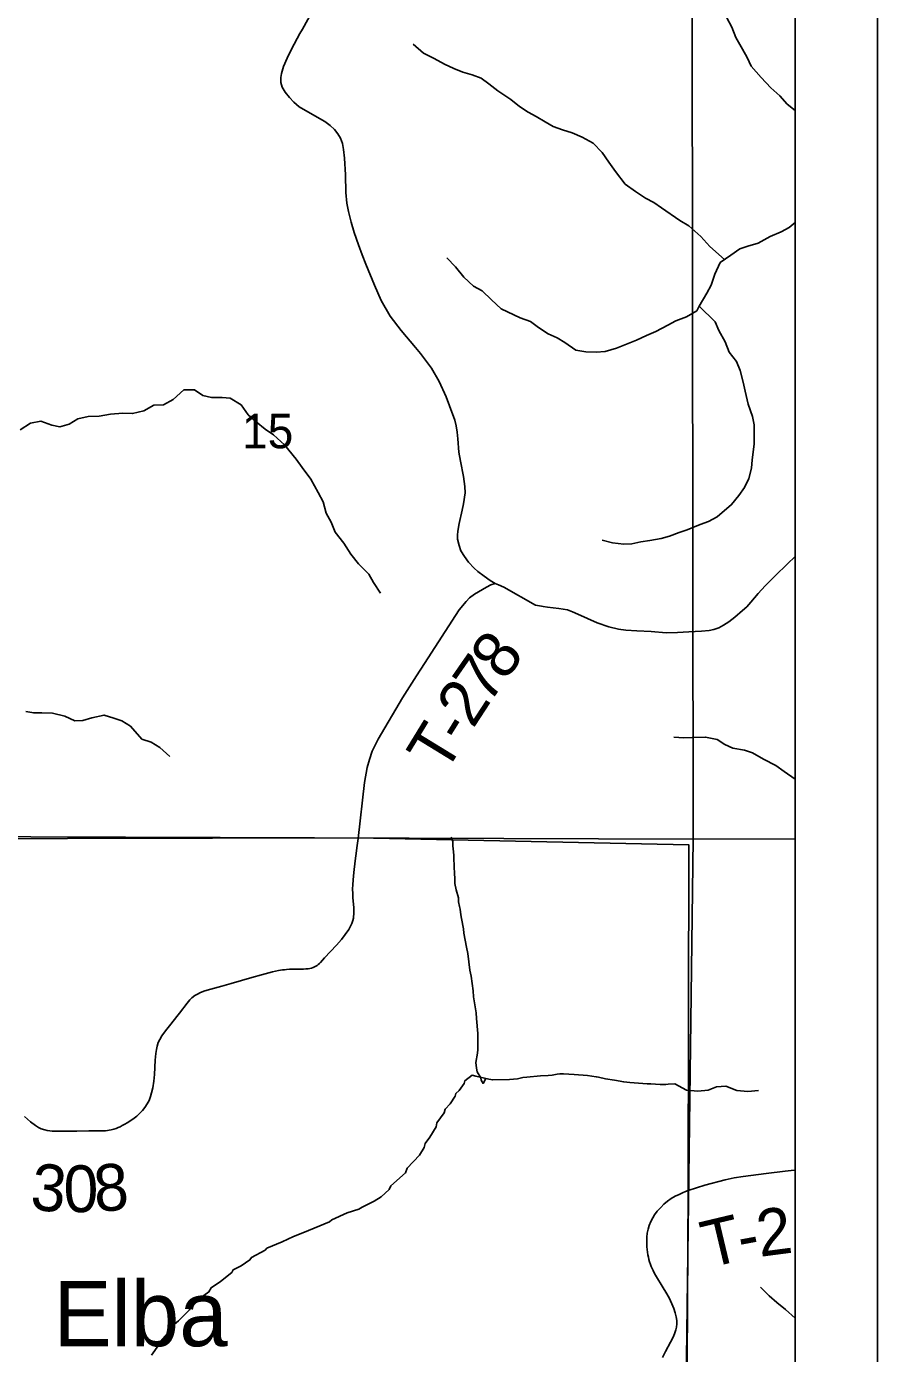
# Model space of a CAD drawing. Extents: x 0 to 34, y 0 to 22.
# Drawn here: x 7.967 to 9, y 14.985 to 16.596 of the extents above; entities that cross this region are included whole.
import ezdxf

# ---------------------------------------------------------------- set-up
doc = ezdxf.new("R2010")
doc.units = 0
for name, color, linetype in [('Default', 7, 'Continuous'), ('GM_X_Minor_River', 7, 'Continuous'), ('GM_X_Rail_Line', 7, 'Continuous'), ('GM_X_Section', 7, 'Continuous'), ('GM_X_Section_Text', 7, 'Continuous'), ('GM_X_Township_Road', 7, 'Continuous'), ('GM_X_Township_Road_Text', 7, 'Continuous'), ('GM_X_Unincorporated_Text', 7, 'Continuous'), ('SH_Cut_Line', 7, 'Continuous'), ('SH_Data', 7, 'Continuous')]:
    doc.layers.add(name, color=color, linetype=linetype)

msp = doc.modelspace()

# ---------------------------------------------------------------- linework, layer by layer
at = {"layer": 'Default'}
for points in [[(8.9, 15.6097), (8.9, 16.6172), (8.7751, 16.6184), (8.7763, 15.6092)], [(8.9, 14.6299), (8.9, 15.6097), (8.7763, 15.6092), (8.7636, 14.6322)]]:
    msp.add_lwpolyline(points, close=True, dxfattribs=at)
at = {"layer": 'GM_X_Minor_River'}
for points in [[(8.9, 16.4939), (8.9, 16.4939), (8.8904, 16.5018), (8.8813, 16.512), (8.8706, 16.5214), (8.8587, 16.5342), (8.8465, 16.5478), (8.8418, 16.5584), (8.8361, 16.5686), (8.828, 16.5826), (8.823, 16.5954), (8.8169, 16.6064)], [(8.8142, 16.313), (8.7963, 16.329), (8.7856, 16.3411), (8.7711, 16.3539), (8.76, 16.3606), (8.7379, 16.3757), (8.7283, 16.3824), (8.7184, 16.3877), (8.7062, 16.3956), (8.6936, 16.4046), (8.6818, 16.42), (8.6737, 16.4314), (8.6657, 16.4431), (8.6546, 16.4544), (8.6412, 16.4615), (8.6294, 16.4671), (8.6176, 16.4705), (8.6062, 16.4745), (8.5963, 16.4802), (8.5856, 16.4869), (8.5757, 16.4922), (8.5651, 16.4989), (8.5548, 16.5072), (8.5391, 16.5177), (8.528, 16.5264), (8.5185, 16.5331), (8.5079, 16.5372), (8.4964, 16.5406), (8.4854, 16.5451), (8.474, 16.5503), (8.4618, 16.557), (8.4488, 16.5638), (8.4362, 16.5747)], [(8.7835, 16.2563), (8.7929, 16.2721), (8.7981, 16.282), (8.8026, 16.2953), (8.8089, 16.3094), (8.8218, 16.3182), (8.8327, 16.3262), (8.8426, 16.3293), (8.8551, 16.3328), (8.8695, 16.3409), (8.8831, 16.3466), (8.8929, 16.352), (8.9, 16.358)], [(8.5431, 16.2534), (8.5313, 16.2643), (8.5198, 16.2749), (8.5092, 16.2809), (8.4977, 16.2918), (8.4874, 16.3042), (8.477, 16.3152)], [(8.7835, 16.2563), (8.7805, 16.2509), (8.768, 16.2437), (8.7551, 16.2386), (8.7453, 16.2332), (8.731, 16.2258), (8.7193, 16.2208), (8.7072, 16.215), (8.6831, 16.2056), (8.6691, 16.2016), (8.6585, 16.2008), (8.646, 16.201), (8.6335, 16.2032), (8.6205, 16.2125), (8.6109, 16.2181), (8.6002, 16.2229), (8.5884, 16.2307), (8.5785, 16.2378), (8.5659, 16.2422), (8.5431, 16.2534)], [(8.7835, 16.2563), (8.8029, 16.2376), (8.8072, 16.2271), (8.8149, 16.2131), (8.82, 16.2006), (8.8288, 16.1894), (8.8331, 16.1784), (8.8367, 16.164), (8.8395, 16.1531), (8.8431, 16.1375), (8.8482, 16.1224), (8.8502, 16.1122), (8.8503, 16.1027), (8.8501, 16.0894), (8.849, 16.0792), (8.848, 16.0697), (8.847, 16.0598), (8.8437, 16.0473), (8.8385, 16.0362), (8.8318, 16.0266), (8.8229, 16.0155), (8.8052, 16.0006), (8.7947, 15.9951), (8.7845, 15.9912), (8.769, 15.985), (8.7592, 15.9818), (8.7475, 15.9772), (8.7373, 15.9744), (8.7237, 15.972), (8.7127, 15.9703), (8.7017, 15.9679), (8.6919, 15.9675), (8.6782, 15.9692), (8.6656, 15.9725)], [(7.959, 16.1063), (7.9714, 16.1144), (7.9839, 16.1168), (7.9972, 16.112), (8.0071, 16.1098), (8.0185, 16.113), (8.029, 16.1195), (8.0415, 16.1227), (8.0547, 16.1229), (8.0684, 16.1253), (8.0835, 16.1266), (8.0953, 16.126), (8.1089, 16.1295), (8.1213, 16.1361), (8.1327, 16.1366), (8.1447, 16.1432), (8.1575, 16.1547), (8.1704, 16.1549), (8.1807, 16.1478), (8.191, 16.1456), (8.2042, 16.1454), (8.2137, 16.1447), (8.2271, 16.1365), (8.2359, 16.1245), (8.2455, 16.1162), (8.2562, 16.1072), (8.2665, 16.1001), (8.2799, 16.0881), (8.2942, 16.0705), (8.3015, 16.0607), (8.3119, 16.0464), (8.3208, 16.0302), (8.327, 16.0189), (8.3305, 16.0052), (8.3367, 15.9943), (8.3414, 15.9822), (8.3518, 15.9687), (8.3603, 15.9555), (8.3699, 15.9438), (8.3822, 15.9311), (8.388, 15.9209), (8.3965, 15.9081)], [(7.9656, 15.7645), (7.9754, 15.7627), (7.9853, 15.7629), (7.9982, 15.7622), (8.013, 15.7586), (8.0252, 15.753), (8.0351, 15.7535), (8.046, 15.7567), (8.0608, 15.7599), (8.0726, 15.7562), (8.0824, 15.7529), (8.0928, 15.7466), (8.1066, 15.7308), (8.118, 15.7271), (8.1283, 15.7208), (8.1406, 15.7095)], [(8.9, 15.6822), (8.8868, 15.6915), (8.8765, 15.6986), (8.8616, 15.7064), (8.8483, 15.7142), (8.8384, 15.7175), (8.8243, 15.72), (8.8148, 15.7241), (8.8053, 15.7305), (8.7912, 15.7333), (8.7749, 15.7328), (8.765, 15.7323), (8.7525, 15.7333)], [(8.5245, 15.3189), (8.5211, 15.3127), (8.5187, 15.3168), (8.5183, 15.3195), (8.514, 15.327), (8.5132, 15.3312), (8.5123, 15.338), (8.5144, 15.3494), (8.5147, 15.354), (8.5148, 15.3673), (8.5147, 15.3734), (8.5129, 15.3916), (8.5128, 15.3984), (8.5094, 15.4177), (8.5089, 15.4253), (8.5067, 15.4431), (8.505, 15.4503), (8.5024, 15.4704), (8.5008, 15.478), (8.4978, 15.4951), (8.4973, 15.5004), (8.4948, 15.5129), (8.494, 15.5174), (8.4931, 15.5242), (8.4923, 15.5276), (8.4911, 15.5333), (8.491, 15.5379), (8.4882, 15.5477), (8.4869, 15.5557), (8.4868, 15.5591), (8.4863, 15.5701), (8.4858, 15.5735), (8.4855, 15.5895), (8.4851, 15.594), (8.4842, 15.6012), (8.4841, 15.6065), (8.4821, 15.6118)], [(8.1183, 14.9827), (8.1272, 14.9953), (8.1294, 14.9995), (8.1406, 15.0123), (8.142, 15.0168), (8.151, 15.0246), (8.1645, 15.0377), (8.1666, 15.0438), (8.188, 15.0597), (8.1906, 15.0647), (8.2022, 15.0721), (8.2157, 15.083), (8.2175, 15.0864), (8.2273, 15.0911), (8.2378, 15.0985), (8.2396, 15.1016), (8.2562, 15.1102), (8.2584, 15.1129), (8.2769, 15.1204), (8.2908, 15.1271), (8.3021, 15.1314), (8.3157, 15.137), (8.3346, 15.1449), (8.3372, 15.1472), (8.356, 15.1558), (8.37, 15.1599), (8.3741, 15.1626), (8.3888, 15.1697), (8.3971, 15.1751), (8.4071, 15.184), (8.409, 15.1886), (8.4269, 15.2041), (8.4287, 15.2098), (8.444, 15.2256), (8.4495, 15.2348), (8.4506, 15.2398), (8.4565, 15.2475), (8.4639, 15.2601), (8.465, 15.2651), (8.4739, 15.277), (8.4749, 15.2816), (8.4809, 15.2881), (8.4872, 15.2973), (8.4879, 15.3004), (8.492, 15.3043), (8.4979, 15.3127), (8.499, 15.3161), (8.5076, 15.3227), (8.5122, 15.3217), (8.5282, 15.3181), (8.5328, 15.3171), (8.5533, 15.3174), (8.5627, 15.3183), (8.5692, 15.3199), (8.5741, 15.3204), (8.5908, 15.3218), (8.5999, 15.3223), (8.6048, 15.3227), (8.6112, 15.324), (8.6143, 15.3244), (8.6188, 15.3245), (8.6317, 15.3235), (8.6477, 15.3223), (8.6584, 15.3209), (8.6614, 15.3202), (8.6698, 15.3185), (8.6808, 15.3167), (8.6919, 15.3146), (8.6991, 15.314), (8.7097, 15.313), (8.7204, 15.3124), (8.7249, 15.3121), (8.736, 15.3115), (8.7428, 15.3116), (8.7458, 15.3117), (8.7538, 15.3122), (8.7679, 15.3044)], [(8.7679, 15.3044), (8.7817, 15.3034), (8.7945, 15.3047), (8.8044, 15.3086), (8.8157, 15.3095), (8.8294, 15.3043), (8.8427, 15.303), (8.8556, 15.3042)], [(8.9, 15.0278), (8.8882, 15.0383), (8.8778, 15.0469), (8.8683, 15.0548), (8.8579, 15.0653)]]:
    msp.add_lwpolyline(points, dxfattribs=at)
at = {"layer": 'GM_X_Rail_Line'}
for points in [[(5.9824, 16.6436), (7.149, 16.6283), (7.6814, 16.6224), (7.7376, 16.622), (7.7377, 16.1663), (7.7446, 16.1373), (7.7538, 15.9954), (7.756, 15.9342), (7.7526, 15.9181), (7.7434, 15.892), (7.7355, 15.6105), (7.8392, 15.6096), (8.369, 15.6108), (8.7708, 15.6025), (8.77, 15.1835), (8.767, 14.6265), (8.9, 14.624), (8.9, 20.9)], [(4.5781, 14.1), (8.76, 14.1), (8.766, 14.6043), (8.767, 14.6265), (8.77, 15.1835), (8.7708, 15.6025), (8.369, 15.6108), (7.8392, 15.6096), (7.7355, 15.6105), (7.7434, 15.892), (7.7526, 15.9181), (7.756, 15.9342), (7.7538, 15.9954), (7.7446, 16.1373), (7.7377, 16.1663), (7.7376, 16.622), (7.6814, 16.6224), (7.149, 16.6283), (5.9824, 16.6436)]]:
    msp.add_lwpolyline(points, dxfattribs=at)
at = {"layer": 'GM_X_Section'}
msp.add_lwpolyline([(7.7506, 16.628), (8.7751, 16.6184), (8.7763, 15.6092), (7.7414, 15.613)], close=True, dxfattribs=at)
at = {"layer": 'GM_X_Township_Road'}
for points in [[(8.3172, 16.6207), (8.3016, 16.5926), (8.2986, 16.5876), (8.2884, 16.5683), (8.2831, 16.5574), (8.2788, 16.5476), (8.2761, 16.5389), (8.2754, 16.534), (8.2755, 16.5282), (8.2771, 16.5224), (8.2805, 16.5163), (8.2859, 16.51), (8.291, 16.5043), (8.2978, 16.4985), (8.3054, 16.4939), (8.3289, 16.4806), (8.3355, 16.4757), (8.3407, 16.4708), (8.3448, 16.4656), (8.3478, 16.4605), (8.3503, 16.454), (8.3517, 16.4468), (8.3527, 16.4361), (8.3538, 16.4161), (8.3542, 16.3945), (8.3556, 16.3815), (8.3574, 16.3714), (8.3609, 16.3585), (8.3646, 16.3458), (8.3699, 16.3311), (8.3742, 16.3189), (8.3787, 16.3074), (8.3891, 16.2818), (8.3971, 16.2632), (8.408, 16.2444), (8.4215, 16.2269), (8.439, 16.2064), (8.4452, 16.1991), (8.4583, 16.1813), (8.4676, 16.165), (8.476, 16.1462), (8.4801, 16.1355), (8.4866, 16.1182), (8.4885, 16.1112), (8.4897, 16.1033), (8.4902, 16.0952), (8.4917, 16.0792), (8.4934, 16.0682), (8.4971, 16.0495), (8.4989, 16.0375), (8.4993, 16.0299), (8.4973, 16.0164), (8.4956, 16.0089), (8.4918, 15.9925), (8.4905, 15.9833), (8.49, 15.9784), (8.4899, 15.9736), (8.4918, 15.9657), (8.4942, 15.9592), (8.4983, 15.9525), (8.5032, 15.9456), (8.51, 15.9385), (8.5148, 15.9342), (8.5225, 15.9285), (8.5296, 15.9234), (8.5355, 15.9198), (8.5398, 15.9181), (8.5461, 15.9151), (8.5846, 15.8934), (8.592, 15.8921), (8.5941, 15.8918)], [(8.5941, 15.8918), (8.5992, 15.8912), (8.6132, 15.8893), (8.6235, 15.8879), (8.6298, 15.8855), (8.6363, 15.8824), (8.6595, 15.8721), (8.6736, 15.8673), (8.6855, 15.8643), (8.6945, 15.8631), (8.7078, 15.8622), (8.7252, 15.8615), (8.7434, 15.8599), (8.7573, 15.8601), (8.7708, 15.8611), (8.7862, 15.8617), (8.7954, 15.8627), (8.8014, 15.864), (8.8072, 15.8659), (8.813, 15.8691), (8.8196, 15.8733), (8.8268, 15.8789), (8.8361, 15.8868), (8.8412, 15.8916), (8.8463, 15.897), (8.8551, 15.9076), (8.8638, 15.917), (8.8758, 15.9292), (8.8906, 15.9436), (8.9, 15.9524)], [(8.5355, 15.9198), (8.5304, 15.918), (8.525, 15.9153), (8.5104, 15.9068), (8.5046, 15.9024), (8.5004, 15.898), (8.4918, 15.8876), (8.4497, 15.8225), (8.4401, 15.8078), (8.4232, 15.7809), (8.3935, 15.7307), (8.3864, 15.716), (8.3829, 15.706), (8.3802, 15.6962), (8.3769, 15.678), (8.3692, 15.6103)], [(7.964, 15.2725), (7.9677, 15.2692), (7.9714, 15.2661), (7.9775, 15.2615), (7.9812, 15.2593), (7.9845, 15.2578), (7.9886, 15.2564), (7.9916, 15.2556), (7.9948, 15.2551), (7.9977, 15.2548), (8.0039, 15.2546), (8.0169, 15.2548), (8.0275, 15.255), (8.0424, 15.2553), (8.0523, 15.2552), (8.0598, 15.2553), (8.0623, 15.2554), (8.0647, 15.2556), (8.067, 15.256), (8.0692, 15.2563), (8.0724, 15.2571), (8.0755, 15.2582), (8.0779, 15.2592), (8.0802, 15.2601), (8.0829, 15.2616), (8.086, 15.2633), (8.0888, 15.265), (8.0956, 15.2694), (8.1005, 15.2732), (8.1043, 15.2765), (8.1072, 15.2797), (8.1103, 15.2836), (8.113, 15.2878), (8.1153, 15.2922), (8.1171, 15.2968), (8.1185, 15.3015), (8.1199, 15.3076), (8.1211, 15.3156), (8.1219, 15.3236), (8.1229, 15.341), (8.1234, 15.3491), (8.1242, 15.354), (8.1252, 15.3582), (8.1266, 15.3623), (8.1285, 15.3662), (8.131, 15.3705), (8.1353, 15.3766), (8.1419, 15.3849), (8.1492, 15.394), (8.1524, 15.3979), (8.1617, 15.4103), (8.1649, 15.4141), (8.1675, 15.4167), (8.1709, 15.4194), (8.1741, 15.4213), (8.178, 15.4232), (8.1832, 15.4252), (8.1903, 15.4274), (8.2036, 15.4309), (8.215, 15.4339), (8.24, 15.4413), (8.252, 15.4447), (8.2652, 15.4481), (8.2691, 15.4491), (8.2725, 15.4497), (8.2749, 15.4501), (8.2774, 15.4505), (8.2799, 15.4508), (8.2823, 15.451), (8.286, 15.4513), (8.2904, 15.4514), (8.3028, 15.4516), (8.3057, 15.4518), (8.3084, 15.452), (8.3106, 15.4524), (8.3126, 15.4529), (8.3146, 15.4535), (8.3162, 15.4542), (8.3181, 15.4551), (8.3195, 15.4561), (8.3208, 15.4571), (8.3222, 15.4584), (8.3235, 15.4597), (8.3286, 15.4651), (8.343, 15.4806), (8.3491, 15.4877), (8.3537, 15.4935), (8.3579, 15.4997), (8.3601, 15.5035), (8.3616, 15.5068), (8.3628, 15.5104), (8.3635, 15.5134), (8.3638, 15.5156), (8.3641, 15.5181), (8.3641, 15.5199), (8.3642, 15.523), (8.364, 15.5261), (8.3637, 15.5304), (8.3632, 15.534), (8.3628, 15.5386), (8.3627, 15.5432), (8.3626, 15.5488), (8.3627, 15.5544), (8.3635, 15.5649), (8.3643, 15.5723), (8.3661, 15.5864), (8.3669, 15.5919), (8.3679, 15.5986), (8.3692, 15.6103)], [(8.7702, 15.1829), (8.7903, 15.1893), (8.8152, 15.1956), (8.8259, 15.1981), (8.8368, 15.1998), (8.8647, 15.2034), (8.8877, 15.2064), (8.8953, 15.2071), (8.9, 15.2076)], [(8.739, 14.9802), (8.7424, 14.9872), (8.7486, 14.9987), (8.7521, 15.0053), (8.7541, 15.0098), (8.7552, 15.0134), (8.756, 15.017), (8.7563, 15.0207), (8.7562, 15.0251), (8.7556, 15.0294), (8.7545, 15.0342), (8.7528, 15.0396), (8.7504, 15.0453), (8.747, 15.0524), (8.7431, 15.0594), (8.7399, 15.0647), (8.7305, 15.0801), (8.729, 15.0826), (8.7276, 15.0856), (8.7263, 15.0882), (8.7252, 15.0906), (8.7243, 15.093), (8.7233, 15.096), (8.7225, 15.099), (8.7219, 15.1019), (8.7213, 15.1048), (8.7207, 15.108), (8.72, 15.1142), (8.7197, 15.1204), (8.7199, 15.1259), (8.7204, 15.1308), (8.7215, 15.1357), (8.7229, 15.1404), (8.7247, 15.145), (8.727, 15.1494), (8.7292, 15.1531), (8.7326, 15.1576), (8.7367, 15.1622), (8.7406, 15.1661), (8.7449, 15.1697), (8.7495, 15.1729), (8.7543, 15.1758), (8.759, 15.1781), (8.7631, 15.18), (8.7667, 15.1815), (8.7702, 15.1829)]]:
    msp.add_lwpolyline(points, dxfattribs=at)
at = {"layer": 'SH_Cut_Line'}
for points in [[(5.9824, 16.6436), (7.149, 16.6283), (7.6814, 16.6224), (7.7376, 16.622), (7.7377, 16.1663), (7.7446, 16.1373), (7.7538, 15.9954), (7.756, 15.9342), (7.7526, 15.9181), (7.7434, 15.892), (7.7355, 15.6105), (7.8392, 15.6096), (8.369, 15.6108), (8.7708, 15.6025), (8.77, 15.1835), (8.767, 14.6265), (8.9, 14.624), (8.9, 20.9)], [(4.5781, 14.1), (8.9, 14.1), (8.9, 14.624), (8.767, 14.6265), (8.77, 15.1835), (8.7708, 15.6025), (8.369, 15.6108), (7.8392, 15.6096), (7.7355, 15.6105), (7.7434, 15.892), (7.7526, 15.9181), (7.756, 15.9342), (7.7538, 15.9954), (7.7446, 16.1373), (7.7377, 16.1663), (7.7376, 16.622), (7.6814, 16.6224), (7.149, 16.6283), (5.9824, 16.6436)]]:
    msp.add_lwpolyline(points, dxfattribs=at)
at = {"layer": 'SH_Data'}
for p, q in [((9, 21), (9, 14)), ((8.9, 20.9), (8.9, 14.1))]:
    msp.add_line(p, q, dxfattribs=at)

# ---------------------------------------------------------------- texts
at = {"layer": 'GM_X_Section_Text'}
msp.add_text('15', height=0.04186, rotation=0, dxfattribs=at).set_placement((8.2283, 16.0839))
at = {"layer": 'GM_X_Township_Road_Text'}
for s, rotation, p in [('8', 53.4465, (8.5473, 15.7999)), ('7', 55.2361, (8.5276, 15.7715)), ('2', 56.9046, (8.5088, 15.7426)), ('T', 58.5166, (8.4745, 15.6869)), ('-', 58.0964, (8.4966, 15.723)), ('3', 354.2629, (7.9699, 15.1599)), ('0', 1.047, (8.012, 15.1561)), ('8', 3.7012, (8.0499, 15.1569)), ('2', 7.4891, (8.857, 15.1021)), ('T', 13.3939, (8.7942, 15.0883)), ('-', 10.5353, (8.8348, 15.098))]:
    msp.add_text(s, height=0.0568, rotation=rotation, dxfattribs=at).set_placement(p)
at = {"layer": 'GM_X_Unincorporated_Text'}
msp.add_text('Elba', height=0.07898, rotation=0, dxfattribs=at).set_placement((7.9994, 14.9937))

doc.saveas('drawing.dxf')
